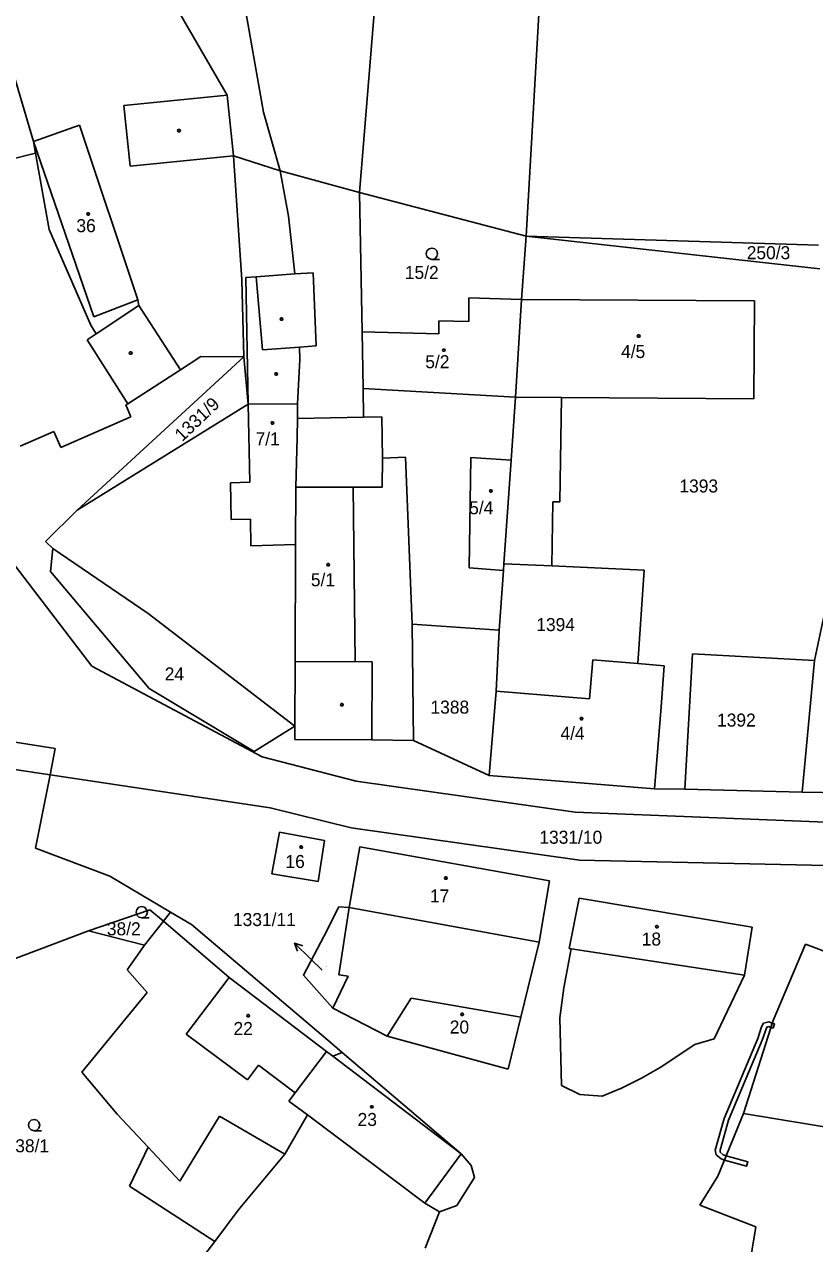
# Model space of a CAD drawing. Extents: x -845995 to -842497, y -1063614 to -1059680.
# Drawn here: x -844541.5 to -844438.3, y -1061526.1 to -1061366.9 of the extents above; entities that cross this region are included whole.
import ezdxf

# ---------------------------------------------------------------- set-up
doc = ezdxf.new("R2010")
doc.units = 0
for name, color, linetype in [('KN_BREMENA', 7, 'Continuous'), ('KN_HRANICE', 7, 'Continuous'), ('KN_KULTURY', 7, 'Continuous'), ('KN_PARCELY', 7, 'Continuous'), ('KN_SLUCKY', 7, 'Continuous'), ('KN_STAVEBNI', 7, 'Continuous')]:
    doc.layers.add(name, color=color, linetype=linetype)

# ---------------------------------------------------------------- blocks, each defined once
blk = doc.blocks.new('304')
blk.add_lwpolyline([(0, 0), (-0.38, 0.1), (-0.65, 0.37), (-0.75, 0.74), (-0.65, 1.11), (-0.38, 1.38), (-0.01, 1.48), (0.36, 1.38), (0.63, 1.11), (0.73, 0.73), (0.63, 0.35), (0.36, 0.08), (-0.02, -0.02), (0.98, -0.02)])
blk = doc.blocks.new('10292')
blk.add_line((0, 3), (0, 0))
blk.add_lwpolyline([(-0.5, 2), (0, 3), (0.5, 2)])
blk = doc.blocks.new('402')
blk.add_lwpolyline([(0.09, 0.15), (0.18, 0), (0.09, -0.15), (-0.09, -0.15), (-0.18, 0), (-0.09, 0.15), (0.09, 0.15)])

msp = doc.modelspace()

# ---------------------------------------------------------------- linework, layer by layer
at = {"layer": 'KN_BREMENA'}
for p, q in [((-844444.23, -1061497.15), (-844443.79, -1061497.31)), ((-844443.79, -1061497.31), (-844443.97, -1061497.88)), ((-844450.08, -1061509.78), (-844445.66, -1061499.33)), ((-844449.81, -1061514.64), (-844450.04, -1061515.2))]:
    msp.add_line(p, q, dxfattribs=at)
for points in [[(-844445.66, -1061499.33), (-844445.18, -1061497.81), (-844444.92, -1061497.33), (-844444.23, -1061497.15)], [(-844443.97, -1061497.88), (-844444.25, -1061497.77), (-844444.52, -1061497.85), (-844445.1, -1061499.53), (-844449.52, -1061509.98)], [(-844450.04, -1061515.2), (-844450.49, -1061515.05), (-844451.14, -1061514.5), (-844451.24, -1061513.89), (-844450.08, -1061509.78)], [(-844449.52, -1061509.98), (-844450.62, -1061513.93), (-844450.58, -1061514.18), (-844450.19, -1061514.51), (-844449.81, -1061514.64)]]:
    msp.add_lwpolyline(points, dxfattribs=at)
for points in [[(-844443.79, -1061497.31), (-844443.51, -1061497.4), (-844443.69, -1061497.97), (-844443.97, -1061497.88)], [(-844449.81, -1061514.64), (-844446.98, -1061515.44), (-844447.14, -1061516.02), (-844450.04, -1061515.2)]]:
    msp.add_lwpolyline(points, close=True, dxfattribs=at)
at = {"layer": 'KN_HRANICE'}
for p, q in [((-844491.42, -1061312.67), (-844497.75, -1061388.86)), ((-844475.97, -1061394.54), (-844471.31, -1061313.26)), ((-844527.05, -1061355.32), (-844515.02, -1061376.12)), ((-844510.28, -1061378.35), (-844513.95, -1061357.42)), ((-844543.93, -1061370.06), (-844540.35, -1061382.16)), ((-844514.22, -1061384.06), (-844515.02, -1061376.12)), ((-844508.11, -1061386.03), (-844510.28, -1061378.35)), ((-844540.35, -1061382.16), (-844540.07, -1061383.72)), ((-844558.34, -1061388.2), (-844540.07, -1061383.72)), ((-844540.07, -1061383.72), (-844538.28, -1061393.67)), ((-844514.22, -1061384.06), (-844513.12, -1061400.25)), ((-844508.11, -1061386.03), (-844514.22, -1061384.06)), ((-844507, -1061391.95), (-844508.11, -1061386.03)), ((-844497.75, -1061388.86), (-844508.11, -1061386.03)), ((-844475.97, -1061394.54), (-844497.75, -1061388.86)), ((-844497.75, -1061388.86), (-844497.39, -1061407.02)), ((-844506.18, -1061399.48), (-844507, -1061391.95)), ((-844538.28, -1061393.67), (-844532.86, -1061406.15)), ((-844475.97, -1061394.54), (-844476.56, -1061402.81)), ((-844475.97, -1061394.54), (-844437.76, -1061395.7)), ((-844437.56, -1061398.83), (-844475.97, -1061394.54)), ((-844506.18, -1061399.48), (-844503.8, -1061399.32)), ((-844503.8, -1061399.32), (-844503.38, -1061408.87)), ((-844512.87, -1061410.29), (-844513.12, -1061400.25)), ((-844476.56, -1061402.81), (-844483.45, -1061402.59)), ((-844483.45, -1061402.59), (-844483.45, -1061405.7)), ((-844476.56, -1061402.81), (-844477.34, -1061415.58)), ((-844446.1, -1061402.99), (-844476.56, -1061402.81)), ((-844446.18, -1061415.77), (-844446.1, -1061402.99)), ((-844532.86, -1061406.15), (-844532.13, -1061407.28)), ((-844483.45, -1061405.7), (-844487.36, -1061405.61)), ((-844487.36, -1061405.61), (-844487.36, -1061407.3)), ((-844533.34, -1061408.07), (-844532.13, -1061407.28)), ((-844528.02, -1061416.46), (-844533.34, -1061408.07)), ((-844487.36, -1061407.3), (-844497.39, -1061407.02)), ((-844497.39, -1061407.02), (-844497.24, -1061414.43)), ((-844503.38, -1061408.87), (-844505.58, -1061409.03)), ((-844505.54, -1061410.63), (-844505.58, -1061409.03)), ((-844512.87, -1061410.29), (-844534.65, -1061430.32)), ((-844521.11, -1061411.99), (-844518.49, -1061410.26)), ((-844518.49, -1061410.26), (-844512.87, -1061410.29)), ((-844512.87, -1061410.29), (-844512.27, -1061416.48)), ((-844505.82, -1061416.42), (-844505.54, -1061410.63)), ((-844528.02, -1061416.46), (-844521.11, -1061411.99)), ((-844497.24, -1061414.43), (-844497.21, -1061418.2)), ((-844477.91, -1061423.8), (-844477.34, -1061415.58)), ((-844477.34, -1061415.58), (-844471.33, -1061415.62)), ((-844471.33, -1061415.62), (-844446.18, -1061415.77)), ((-844512.27, -1061416.48), (-844534.65, -1061430.32)), ((-844528.29, -1061416.58), (-844528.02, -1061416.46)), ((-844527.6, -1061418.16), (-844528.29, -1061416.58)), ((-844505.84, -1061418.35), (-844505.82, -1061416.42)), ((-844536.76, -1061422.14), (-844527.6, -1061418.16)), ((-844505.86, -1061420.82), (-844505.84, -1061418.35)), ((-844497.21, -1061418.2), (-844494.81, -1061418.12)), ((-844494.81, -1061418.12), (-844494.74, -1061423.55)), ((-844542.06, -1061421.97), (-844537.66, -1061420.06)), ((-844537.66, -1061420.06), (-844536.76, -1061422.14)), ((-844506.07, -1061427.33), (-844505.86, -1061420.82)), ((-844491.72, -1061423.39), (-844494.74, -1061423.55)), ((-844491.72, -1061423.39), (-844490.87, -1061445.21)), ((-844483.19, -1061423.43), (-844483.4, -1061437.88)), ((-844477.91, -1061423.8), (-844483.19, -1061423.43)), ((-844478.86, -1061437.32), (-844477.91, -1061423.8)), ((-844506.1, -1061434.82), (-844506.07, -1061427.33)), ((-844534.65, -1061430.32), (-844538.76, -1061434.44)), ((-844538.76, -1061434.44), (-844537.81, -1061435.32)), ((-844506.1, -1061434.82), (-844506.16, -1061450.12)), ((-844537.81, -1061435.32), (-844538.1, -1061438.35)), ((-844537.81, -1061435.32), (-844525.34, -1061443.83)), ((-844483.4, -1061437.88), (-844478.92, -1061438.19)), ((-844479.46, -1061446.01), (-844478.92, -1061438.19)), ((-844478.86, -1061437.32), (-844478.92, -1061438.19)), ((-844472.62, -1061437.6), (-844478.86, -1061437.32)), ((-844472.62, -1061437.6), (-844460.54, -1061438.15)), ((-844461.37, -1061450.37), (-844460.54, -1061438.15)), ((-844438.29, -1061449.97), (-844435.49, -1061436.86)), ((-844538.1, -1061438.35), (-844525.21, -1061453.61)), ((-844525.34, -1061443.83), (-844506.19, -1061458.53)), ((-844479.46, -1061446.01), (-844490.87, -1061445.21)), ((-844490.87, -1061445.21), (-844490.69, -1061460.43)), ((-844479.88, -1061453.98), (-844479.46, -1061446.01)), ((-844454.2, -1061449.07), (-844455.23, -1061466.77)), ((-844454.2, -1061449.07), (-844438.29, -1061449.97)), ((-844506.16, -1061450.12), (-844506.19, -1061458.53)), ((-844467.66, -1061454.96), (-844467.22, -1061449.89)), ((-844467.22, -1061449.89), (-844461.37, -1061450.37)), ((-844461.37, -1061450.37), (-844457.92, -1061450.65)), ((-844458.3, -1061456.01), (-844457.92, -1061450.65)), ((-844438.29, -1061449.97), (-844439.9, -1061467.16)), ((-844525.21, -1061453.61), (-844511.48, -1061461.86)), ((-844480.79, -1061464.98), (-844479.88, -1061453.98)), ((-844467.66, -1061454.96), (-844479.88, -1061453.98)), ((-844459.17, -1061466.7), (-844458.3, -1061456.01)), ((-844511.48, -1061461.86), (-844506.19, -1061458.53)), ((-844506.19, -1061458.53), (-844506.2, -1061460.27)), ((-844544.65, -1061460.34), (-844537.49, -1061461.47)), ((-844506.2, -1061460.27), (-844496.12, -1061460.31)), ((-844490.69, -1061460.43), (-844496.12, -1061460.31)), ((-844490.69, -1061460.43), (-844480.79, -1061464.98)), ((-844537.49, -1061461.47), (-844538.17, -1061464.9)), ((-844538.17, -1061464.9), (-844540.06, -1061474.46)), ((-844480.79, -1061464.98), (-844459.17, -1061466.7)), ((-844455.23, -1061466.77), (-844459.17, -1061466.7)), ((-844439.9, -1061467.16), (-844455.23, -1061466.77)), ((-844439.9, -1061467.16), (-844426.7, -1061467.38)), ((-844509.17, -1061477.83), (-844508.18, -1061472.36)), ((-844508.18, -1061472.36), (-844502.29, -1061473.49)), ((-844540.06, -1061474.46), (-844530.36, -1061478.14)), ((-844502.29, -1061473.49), (-844503.13, -1061478.82)), ((-844499.1, -1061482.2), (-844497.69, -1061474.31)), ((-844472.91, -1061478.73), (-844497.69, -1061474.31)), ((-844503.13, -1061478.82), (-844509.17, -1061477.83)), ((-844522.43, -1061482.82), (-844530.36, -1061478.14)), ((-844472.91, -1061478.73), (-844474.24, -1061486.74)), ((-844470.33, -1061487.58), (-844469.04, -1061480.99)), ((-844469.04, -1061480.99), (-844446.4, -1061484.8)), ((-844525.13, -1061482.52), (-844533.17, -1061485.27)), ((-844523.35, -1061484.01), (-844525.13, -1061482.52)), ((-844523.35, -1061484.01), (-844522.43, -1061482.82)), ((-844522.43, -1061482.82), (-844519.71, -1061484.45)), ((-844500.45, -1061491), (-844499.1, -1061482.2)), ((-844523.35, -1061484.01), (-844525.84, -1061487.14)), ((-844519.71, -1061484.45), (-844501.32, -1061500.02)), ((-844533.17, -1061485.27), (-844552.79, -1061492.69)), ((-844525.84, -1061487.14), (-844533.17, -1061485.27)), ((-844447.44, -1061491.04), (-844446.4, -1061484.8)), ((-844525.84, -1061487.14), (-844528.09, -1061490.36)), ((-844476.64, -1061496.54), (-844474.24, -1061486.74)), ((-844471.01, -1061492.7), (-844470.08, -1061487.62)), ((-844470.08, -1061487.62), (-844470.33, -1061487.58)), ((-844439.44, -1061487), (-844443.69, -1061496.99)), ((-844439.44, -1061487), (-844435.75, -1061488.39)), ((-844528.09, -1061490.36), (-844525.48, -1061493.33)), ((-844501.2, -1061495.38), (-844499.23, -1061491.2)), ((-844499.23, -1061491.2), (-844500.45, -1061491)), ((-844447.44, -1061491.04), (-844451.38, -1061499.36)), ((-844525.48, -1061493.33), (-844534.02, -1061503.71)), ((-844494.12, -1061499.03), (-844490.99, -1061494.04)), ((-844490.99, -1061494.04), (-844476.64, -1061496.54)), ((-844471.54, -1061496.63), (-844471.01, -1061492.7)), ((-844494.12, -1061499.03), (-844501.2, -1061495.38)), ((-844478.31, -1061503.35), (-844476.64, -1061496.54)), ((-844471.35, -1061505.46), (-844471.54, -1061496.63)), ((-844447.53, -1061509.13), (-844443.69, -1061496.99)), ((-844501.32, -1061500.02), (-844499.99, -1061501.15)), ((-844478.31, -1061503.35), (-844494.12, -1061499.03)), ((-844453.89, -1061500.11), (-844458.45, -1061503.11)), ((-844451.38, -1061499.36), (-844453.89, -1061500.11)), ((-844502.06, -1061501.02), (-844506.15, -1061506.42)), ((-844501.23, -1061501.65), (-844502.06, -1061501.02)), ((-844501.23, -1061501.65), (-844499.99, -1061501.15)), ((-844499.99, -1061501.15), (-844484.46, -1061514.39)), ((-844458.45, -1061503.11), (-844460.89, -1061504.52)), ((-844534.02, -1061503.71), (-844529.4, -1061509.21)), ((-844460.89, -1061504.52), (-844463.48, -1061505.8)), ((-844506.15, -1061506.42), (-844506.96, -1061507.5)), ((-844468.92, -1061506.65), (-844471.35, -1061505.46)), ((-844466.04, -1061506.84), (-844468.92, -1061506.65)), ((-844463.48, -1061505.8), (-844466.04, -1061506.84)), ((-844506.96, -1061507.5), (-844504.54, -1061509.31)), ((-844529.4, -1061509.21), (-844525.36, -1061513.51)), ((-844507.51, -1061514.42), (-844504.54, -1061509.31)), ((-844447.53, -1061509.13), (-844450.91, -1061517.31)), ((-844447.53, -1061509.13), (-844425.81, -1061512.7)), ((-844525.36, -1061513.51), (-844527.77, -1061518.6)), ((-844507.51, -1061514.42), (-844513.59, -1061521.76)), ((-844484.46, -1061514.39), (-844483.12, -1061515.92)), ((-844483.12, -1061515.92), (-844482.71, -1061517.5)), ((-844482.71, -1061517.5), (-844485.03, -1061521.15)), ((-844450.91, -1061517.31), (-844453.26, -1061521.11)), ((-844527.77, -1061518.6), (-844516.66, -1061525.83)), ((-844453.26, -1061521.11), (-844445.93, -1061523.92)), ((-844513.59, -1061521.76), (-844516.66, -1061525.83)), ((-844487.27, -1061521.98), (-844489.14, -1061526.71)), ((-844485.03, -1061521.15), (-844487.27, -1061521.98)), ((-844445.93, -1061523.92), (-844447.49, -1061533.39)), ((-844516.66, -1061525.83), (-844519.11, -1061529.08))]:
    msp.add_line(p, q, dxfattribs=at)
msp.add_lwpolyline([(-844501.2, -1061495.38), (-844505.07, -1061491.05), (-844502.36, -1061485.93), (-844500.43, -1061482.14), (-844499.1, -1061482.2)], dxfattribs=at)
at = {"layer": 'KN_PARCELY'}
msp.add_line((-844502.62, -1061490.42), (-844504.08, -1061488.98), dxfattribs=at)
at = {"layer": 'KN_SLUCKY'}
for p, q in [((-844515.02, -1061376.12), (-844528.52, -1061377.48)), ((-844528.52, -1061377.48), (-844527.69, -1061385.41)), ((-844534.32, -1061380.05), (-844540.35, -1061382.16)), ((-844526.69, -1061402.86), (-844534.32, -1061380.05)), ((-844540.35, -1061382.16), (-844532.45, -1061405.06)), ((-844527.69, -1061385.41), (-844514.22, -1061384.06)), ((-844512.59, -1061399.96), (-844511.22, -1061399.86)), ((-844512.27, -1061416.48), (-844512.59, -1061399.96)), ((-844511.22, -1061399.86), (-844506.18, -1061399.48)), ((-844510.4, -1061409.39), (-844511.22, -1061399.86)), ((-844532.45, -1061405.06), (-844526.69, -1061402.86)), ((-844526.55, -1061403.62), (-844526.69, -1061402.86)), ((-844532.13, -1061407.28), (-844526.55, -1061403.62)), ((-844521.11, -1061411.99), (-844526.55, -1061403.62)), ((-844505.58, -1061409.03), (-844510.4, -1061409.39)), ((-844477.34, -1061415.58), (-844497.24, -1061414.43)), ((-844471.57, -1061429.24), (-844471.33, -1061415.62)), ((-844532.72, -1061450.71), (-844558.62, -1061416.89)), ((-844512.27, -1061416.48), (-844505.82, -1061416.42)), ((-844512.27, -1061416.48), (-844512.08, -1061426.69)), ((-844497.21, -1061418.2), (-844505.84, -1061418.35)), ((-844494.78, -1061427.32), (-844494.74, -1061423.55)), ((-844512.08, -1061426.69), (-844514.58, -1061426.74)), ((-844514.58, -1061426.74), (-844514.49, -1061431.54)), ((-844506.07, -1061427.33), (-844498.54, -1061427.32)), ((-844498.54, -1061427.32), (-844494.78, -1061427.32)), ((-844498.31, -1061450.11), (-844498.54, -1061427.32)), ((-844472.62, -1061437.6), (-844472.47, -1061429.23)), ((-844472.47, -1061429.23), (-844471.57, -1061429.24)), ((-844514.49, -1061431.54), (-844511.99, -1061431.5)), ((-844511.99, -1061431.5), (-844511.92, -1061435)), ((-844511.92, -1061435), (-844506.1, -1061434.82)), ((-844510.47, -1061462.54), (-844532.72, -1061450.71)), ((-844498.31, -1061450.11), (-844506.16, -1061450.12)), ((-844496.08, -1061450.13), (-844498.31, -1061450.11)), ((-844496.12, -1061460.31), (-844496.08, -1061450.13)), ((-844558.37, -1061461.86), (-844538.17, -1061464.9)), ((-844510.47, -1061462.54), (-844498.15, -1061465.73)), ((-844538.17, -1061464.9), (-844509.4, -1061469.22)), ((-844498.15, -1061465.73), (-844469.55, -1061469.78)), ((-844509.4, -1061469.22), (-844498.84, -1061471.8)), ((-844469.55, -1061469.78), (-844431.61, -1061471.3)), ((-844498.84, -1061471.8), (-844468.98, -1061476.02)), ((-844468.98, -1061476.02), (-844432.78, -1061476.81)), ((-844474.24, -1061486.74), (-844499.1, -1061482.2)), ((-844514.78, -1061491.36), (-844523.35, -1061484.01)), ((-844447.44, -1061491.04), (-844470.08, -1061487.62)), ((-844514.78, -1061491.36), (-844520.39, -1061498.74)), ((-844509.14, -1061495.64), (-844514.78, -1061491.36)), ((-844509.14, -1061495.64), (-844502.06, -1061501.02)), ((-844520.39, -1061498.74), (-844512.39, -1061504.74)), ((-844501.23, -1061501.65), (-844484.46, -1061514.39)), ((-844512.39, -1061504.74), (-844510.95, -1061502.82)), ((-844510.95, -1061502.82), (-844506.15, -1061506.42)), ((-844521.2, -1061517.94), (-844516.05, -1061509.47)), ((-844516.05, -1061509.47), (-844507.51, -1061514.42)), ((-844504.54, -1061509.31), (-844489.21, -1061520.82)), ((-844525.36, -1061513.51), (-844521.2, -1061517.94)), ((-844484.46, -1061514.39), (-844489.21, -1061520.82)), ((-844487.27, -1061521.98), (-844489.21, -1061520.82))]:
    msp.add_line(p, q, dxfattribs=at)
at = {"layer": 'KN_STAVEBNI'}
for p, q in [((-844534.32, -1061380.05), (-844540.35, -1061382.16)), ((-844526.69, -1061402.86), (-844534.32, -1061380.05)), ((-844540.35, -1061382.16), (-844532.45, -1061405.06)), ((-844532.45, -1061405.06), (-844526.69, -1061402.86)), ((-844476.56, -1061402.81), (-844483.45, -1061402.59)), ((-844483.45, -1061402.59), (-844483.45, -1061405.7)), ((-844476.56, -1061402.81), (-844477.34, -1061415.58)), ((-844476.56, -1061402.81), (-844477.34, -1061415.58)), ((-844446.1, -1061402.99), (-844476.56, -1061402.81)), ((-844446.18, -1061415.77), (-844446.1, -1061402.99)), ((-844483.45, -1061405.7), (-844487.36, -1061405.61)), ((-844487.36, -1061405.61), (-844487.36, -1061407.3)), ((-844487.36, -1061407.3), (-844497.39, -1061407.02)), ((-844497.39, -1061407.02), (-844497.24, -1061414.43)), ((-844477.34, -1061415.58), (-844497.24, -1061414.43)), ((-844477.34, -1061415.58), (-844471.33, -1061415.62)), ((-844471.33, -1061415.62), (-844446.18, -1061415.77)), ((-844512.27, -1061416.48), (-844505.82, -1061416.42)), ((-844512.27, -1061416.48), (-844512.08, -1061426.69)), ((-844505.84, -1061418.35), (-844505.82, -1061416.42)), ((-844505.86, -1061420.82), (-844505.84, -1061418.35)), ((-844506.07, -1061427.33), (-844505.86, -1061420.82)), ((-844483.19, -1061423.43), (-844483.4, -1061437.88)), ((-844477.91, -1061423.8), (-844483.19, -1061423.43)), ((-844478.86, -1061437.32), (-844477.91, -1061423.8)), ((-844512.08, -1061426.69), (-844514.58, -1061426.74)), ((-844514.58, -1061426.74), (-844514.49, -1061431.54)), ((-844506.1, -1061434.82), (-844506.07, -1061427.33)), ((-844506.1, -1061434.82), (-844506.07, -1061427.33)), ((-844506.07, -1061427.33), (-844498.54, -1061427.32)), ((-844498.31, -1061450.11), (-844498.54, -1061427.32)), ((-844514.49, -1061431.54), (-844511.99, -1061431.5)), ((-844511.99, -1061431.5), (-844511.92, -1061435)), ((-844511.92, -1061435), (-844506.1, -1061434.82)), ((-844506.1, -1061434.82), (-844506.16, -1061450.12)), ((-844483.4, -1061437.88), (-844478.92, -1061438.19)), ((-844478.86, -1061437.32), (-844478.92, -1061438.19)), ((-844498.31, -1061450.11), (-844506.16, -1061450.12)), ((-844467.66, -1061454.96), (-844467.22, -1061449.89)), ((-844467.22, -1061449.89), (-844461.37, -1061450.37)), ((-844461.37, -1061450.37), (-844457.92, -1061450.65)), ((-844458.3, -1061456.01), (-844457.92, -1061450.65)), ((-844480.79, -1061464.98), (-844479.88, -1061453.98)), ((-844467.66, -1061454.96), (-844479.88, -1061453.98)), ((-844459.17, -1061466.7), (-844458.3, -1061456.01)), ((-844480.79, -1061464.98), (-844459.17, -1061466.7)), ((-844509.17, -1061477.83), (-844508.18, -1061472.36)), ((-844508.18, -1061472.36), (-844502.29, -1061473.49)), ((-844502.29, -1061473.49), (-844503.13, -1061478.82)), ((-844499.1, -1061482.2), (-844497.69, -1061474.31)), ((-844472.91, -1061478.73), (-844497.69, -1061474.31)), ((-844503.13, -1061478.82), (-844509.17, -1061477.83)), ((-844472.91, -1061478.73), (-844474.24, -1061486.74)), ((-844470.33, -1061487.58), (-844469.04, -1061480.99)), ((-844469.04, -1061480.99), (-844446.4, -1061484.8)), ((-844474.24, -1061486.74), (-844499.1, -1061482.2)), ((-844447.44, -1061491.04), (-844446.4, -1061484.8)), ((-844470.08, -1061487.62), (-844470.33, -1061487.58)), ((-844447.44, -1061491.04), (-844470.08, -1061487.62)), ((-844514.78, -1061491.36), (-844520.39, -1061498.74)), ((-844509.14, -1061495.64), (-844514.78, -1061491.36)), ((-844494.12, -1061499.03), (-844490.99, -1061494.04)), ((-844490.99, -1061494.04), (-844476.64, -1061496.54)), ((-844509.14, -1061495.64), (-844502.06, -1061501.02)), ((-844478.31, -1061503.35), (-844476.64, -1061496.54)), ((-844520.39, -1061498.74), (-844512.39, -1061504.74)), ((-844478.31, -1061503.35), (-844494.12, -1061499.03)), ((-844502.06, -1061501.02), (-844506.15, -1061506.42)), ((-844502.06, -1061501.02), (-844506.15, -1061506.42)), ((-844501.23, -1061501.65), (-844502.06, -1061501.02)), ((-844501.23, -1061501.65), (-844484.46, -1061514.39)), ((-844512.39, -1061504.74), (-844510.95, -1061502.82)), ((-844510.95, -1061502.82), (-844506.15, -1061506.42)), ((-844506.15, -1061506.42), (-844506.96, -1061507.5)), ((-844506.96, -1061507.5), (-844504.54, -1061509.31)), ((-844504.54, -1061509.31), (-844489.21, -1061520.82)), ((-844484.46, -1061514.39), (-844489.21, -1061520.82))]:
    msp.add_line(p, q, dxfattribs=at)

# ---------------------------------------------------------------- block references
at = {"layer": 'KN_KULTURY'}
for name, p in [('402', (-844521.32, -1061380.76)), ('402', (-844533.18, -1061391.64)), ('304', (-844488.27, -1061397.57)), ('402', (-844507.92, -1061405.37)), ('402', (-844461.25, -1061407.59)), ('402', (-844527.64, -1061409.81)), ('402', (-844486.73, -1061409.43)), ('402', (-844508.62, -1061412.53)), ('402', (-844509.11, -1061418.94)), ('402', (-844480.56, -1061427.82)), ('402', (-844501.82, -1061437.46)), ('402', (-844500.03, -1061455.74)), ('402', (-844468.72, -1061457.55)), ('402', (-844505.35, -1061474.33)), ('402', (-844486.45, -1061478.37)), ('304', (-844526.18, -1061483.57)), ('402', (-844458.86, -1061484.72)), ('402', (-844512.27, -1061496.36)), ('402', (-844484.32, -1061496.19)), ('402', (-844496.13, -1061508.25)), ('304', (-844540.25, -1061511.37))]:
    msp.add_blockref(name, p, dxfattribs=at)
at = {"layer": 'KN_PARCELY', "rotation": 45.492849}
msp.add_blockref('10292', (-844504.08, -1061488.98), dxfattribs=at)

# ---------------------------------------------------------------- texts
at = {"layer": 'KN_PARCELY'}
for s, height, p in [('36', 1.7, (-844534.73, -1061394.02)), ('250/3', 1.7, (-844447.13, -1061397.55)), ('15/2', 1.7, (-844491.81, -1061400.13)), ('4/5', 1.7, (-844463.55, -1061410.46)), ('5/2', 1.7, (-844489.14, -1061411.79)), ('7/1', 1.7, (-844511.31, -1061421.86)), ('1393', 1.7, (-844455.93, -1061428.02)), ('5/4', 1.7, (-844483.4, -1061430.86)), ('5/1', 1.7, (-844504.09, -1061440.27)), ('1394', 1.7, (-844474.63, -1061446.12)), ('24', 1.7, (-844523.19, -1061452.57)), ('1388', 1.7, (-844488.46, -1061456.9)), ('1392', 1.7, (-844451.01, -1061458.59)), ('4/4', 1.7, (-844471.47, -1061460.32)), ('1331/10', 1.7, (-844474.23, -1061473.89)), ('16', 1.7, (-844507.41, -1061477.06)), ('17', 1.7, (-844488.53, -1061481.56)), ('1331/11', 1.7, (-844514.27, -1061484.64)), ('38/2', 1.7, (-844530.75, -1061485.85)), ('18', 1.7, (-844460.85, -1061487.19)), ('1331/11', 0.1, (-844502.51, -1061489.99)), ('22', 1.7, (-844514.2, -1061498.87)), ('20', 1.7, (-844485.94, -1061498.68)), ('23', 1.7, (-844497.98, -1061510.75)), ('38/1', 1.7, (-844542.72, -1061514.19))]:
    msp.add_text(s, height=height, dxfattribs=at).set_placement(p)
msp.add_text('1331/9', height=1.7, rotation=43.717, dxfattribs=at).set_placement((-844520.9, -1061421.46))

doc.saveas('drawing.dxf')
